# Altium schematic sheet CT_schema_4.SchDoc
size 312 x 277 mm
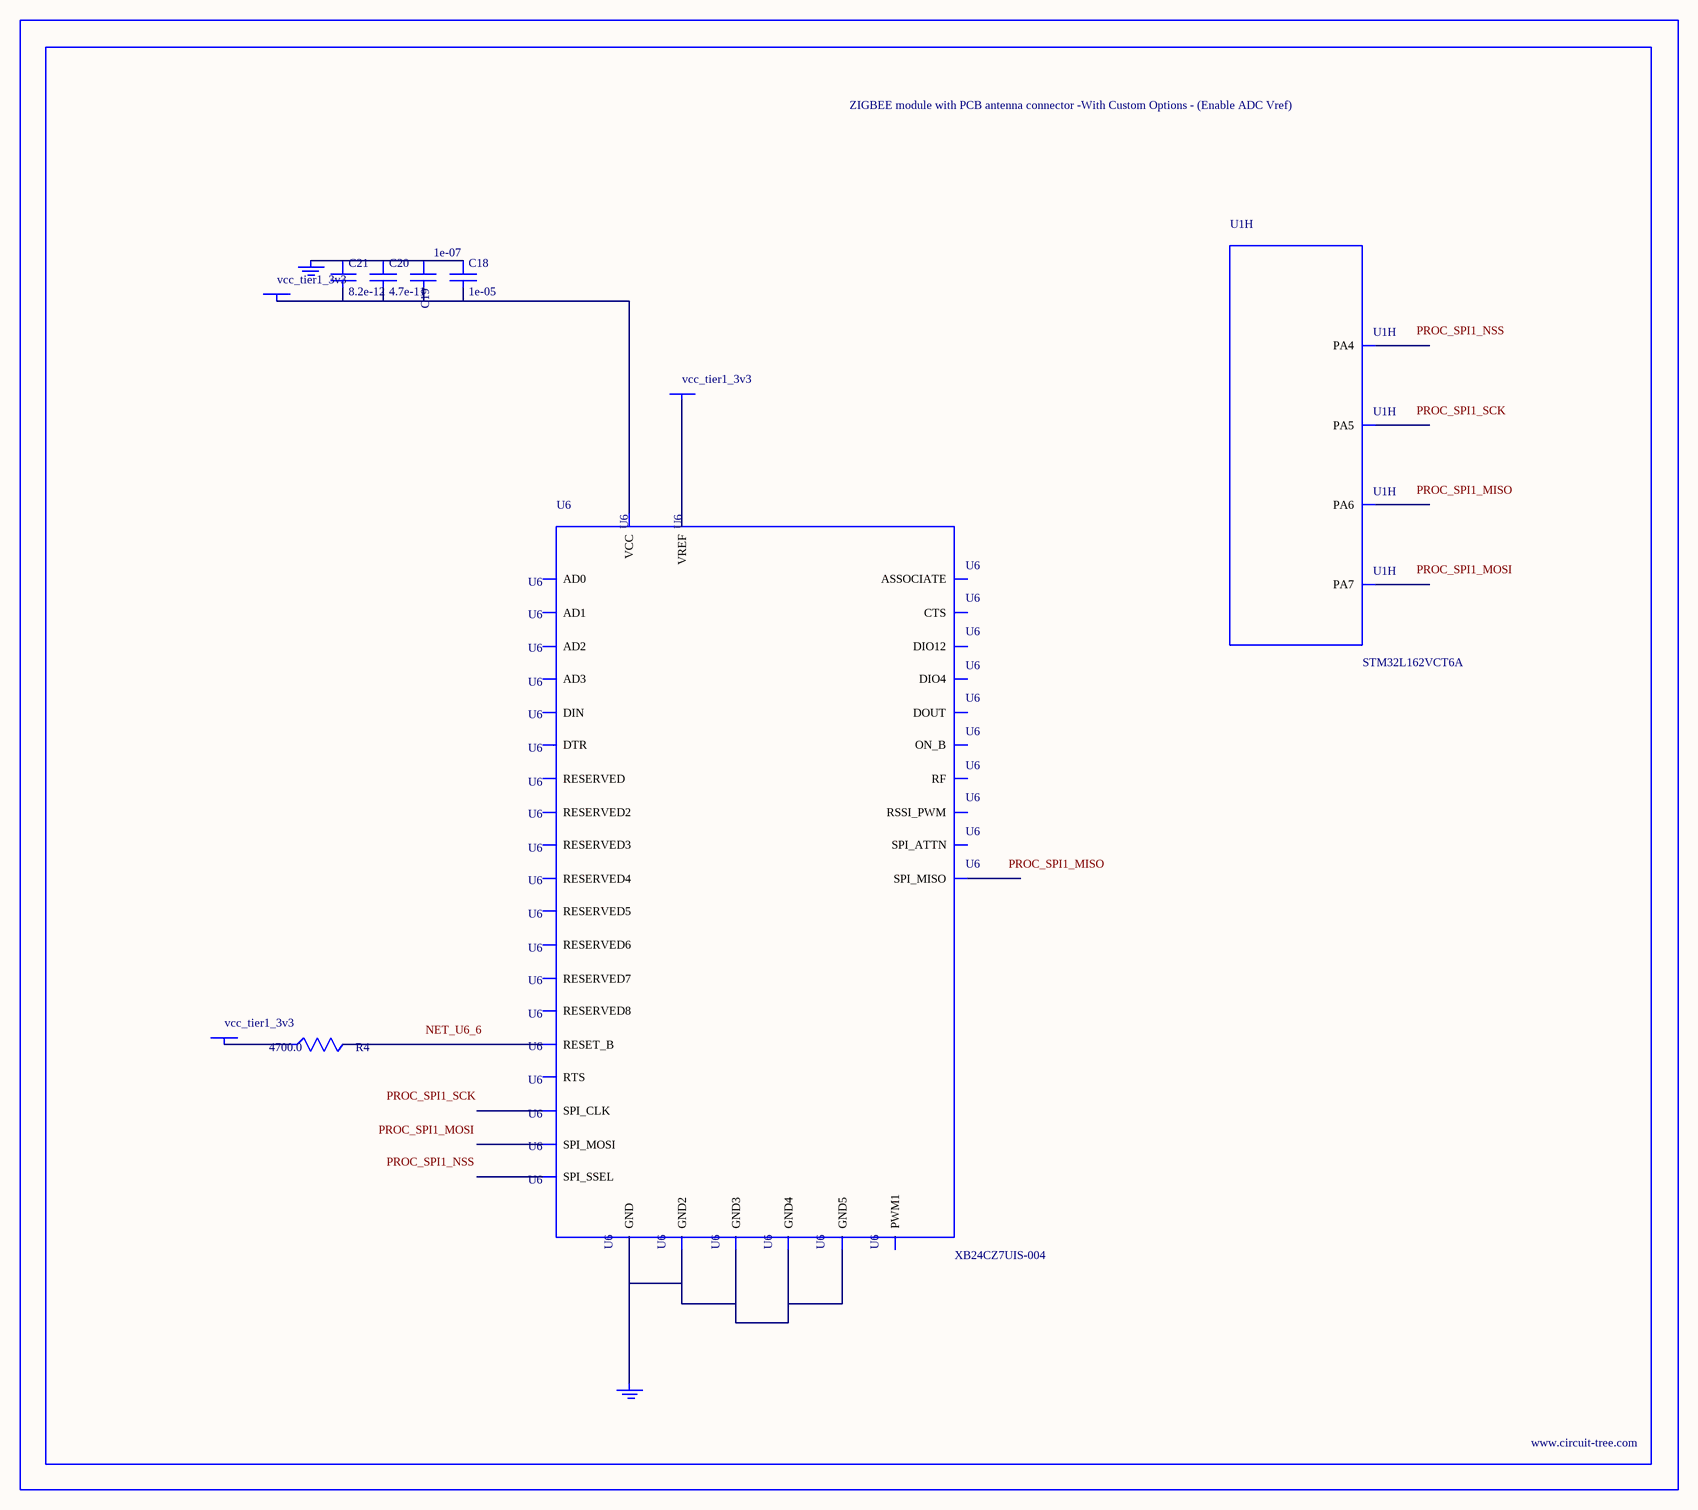
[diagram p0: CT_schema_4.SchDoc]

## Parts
BORDER3  (no value)
C18  1e-05  [C0805]
C19  1e-07  [C0402]
C20  4.7e-11  [C0402]
C21  8.2e-12  [C0603]
GND_INSTANCE_3_0  (no value)
GND_INSTANCE_3_1  (no value)
POWER_INSTANCE_3_0  vcc_tier1_3v3
POWER_INSTANCE_3_1  vcc_tier1_3v3
POWER_INSTANCE_3_2  vcc_tier1_3v3
R4  4700.0  [R0603]
U1  STM32L162VCT6A  [LQFP100]  (part H of 9)
U6  XB24CZ7UIS-004  [XB24CZ7UIS-004]

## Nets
NetC18_1: C18.1 C19.1 C20.1 C21.1 GND_INSTANCE_3_0.0(GND)
NetC18_2: C18.2 C19.2 C20.2 C21.2 POWER_INSTANCE_3_0.0(PWR) U6.2(VCC)
NetGND_INSTANCE_3_1_0: GND_INSTANCE_3_1.0(GND) U6.1(GND) U6.11(GND2) U6.13(GND3) U6.22(GND4) U6.35(GND5)
NetPOWER_INSTANCE_3_1_0: POWER_INSTANCE_3_1.0(PWR) R4.1
NetPOWER_INSTANCE_3_2_0: POWER_INSTANCE_3_2.0(PWR) U6.27(VREF)
NetR4_2: R4.2 U6.6(RESET_B)

Not connected (* = marked no-connect by the designer): U1 29(PA4) 30(PA5) 31(PA6) 32(PA7); U6 3(DOUT) 4(DIN) 5(DIO12) 7(RSSI_PWM) 8(PWM1) 9(RESERVED) 10(DTR) 12(SPI_ATTN) 14(SPI_CLK) 15(SPI_SSEL) 16(SPI_MOSI) 17(SPI_MISO) 18(RESERVED2) 19(RESERVED3) 20(RESERVED4) 21(RESERVED5) 23(RESERVED6) 24(DIO4) 25(CTS) 26(ON_B) 28(ASSOCIATE) 29(RTS) 30(AD3) 31(AD2) 32(AD1) 33(AD0) 34(RESERVED7) 36(RF) 37(RESERVED8)

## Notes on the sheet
- Labels drawn without touching a wire or pin: NET_U6_6, PROC_SPI1_MISO, PROC_SPI1_MOSI, PROC_SPI1_NSS, PROC_SPI1_SCK

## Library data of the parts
BORDER3 = BORDER_PAGE3
C18 = C0805C106K8RACTU
C19 = C0402C104K3RACTU
C20 = C0402C470K3RAC
C21 = 06035J8R2BBTTR
GND_INSTANCE_3_0 GND_INSTANCE_3_1 = GND
POWER_INSTANCE_3_0-POWER_INSTANCE_3_2 = PWR
R4 = RC0603JR-074K7L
